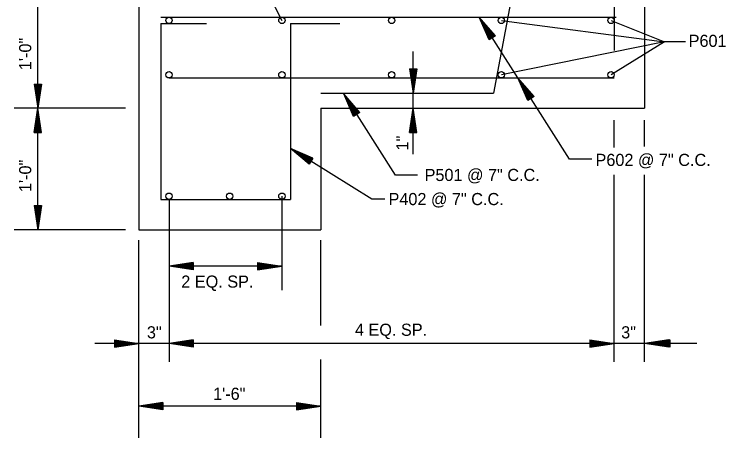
# Model space of a CAD drawing. Extents: x 714919 to 718439, y 1619644 to 1621844.
# Drawn here: x 717030 to 717616, y 1620465 to 1620814 of the extents above; entities that cross this region are included whole.
import ezdxf

# ---------------------------------------------------------------- set-up
doc = ezdxf.new("R2010")
doc.units = 0
doc.layers.add('R_Dimension', color=7, linetype='Continuous')
doc.layers.add('R_Draft', color=7, linetype='Continuous')

msp = doc.modelspace()

# ---------------------------------------------------------------- linework, layer by layer
at = {"layer": 'R_Dimension'}
for p, q in [((717426.61, 1620796.16), (717413.33, 1620811.42)), ((717421.55, 1620792.94), (717413.33, 1620811.42)), ((717426.19, 1620795.89), (717415.13, 1620808.6)), ((717421.97, 1620793.2), (717415.13, 1620808.6)), ((717422.4, 1620793.48), (717416.98, 1620805.7)), ((717425.76, 1620795.62), (717416.98, 1620805.7)), ((717425.34, 1620795.35), (717418.77, 1620802.89)), ((717422.82, 1620793.75), (717418.77, 1620802.89)), ((717423.25, 1620794.02), (717420.59, 1620800.03)), ((717424.9, 1620795.07), (717420.59, 1620800.03)), ((717426.61, 1620796.16), (717421.55, 1620792.94)), ((717423.68, 1620794.3), (717422.38, 1620797.21)), ((717424.48, 1620794.8), (717422.38, 1620797.21)), ((717355.85, 1620768.92), (717358.85, 1620748.92)), ((717355.85, 1620768.92), (717361.85, 1620768.92)), ((717356.35, 1620768.92), (717358.85, 1620752.26)), ((717356.86, 1620768.92), (717358.85, 1620755.7)), ((717357.36, 1620768.92), (717358.85, 1620759.03)), ((717357.88, 1620768.92), (717358.85, 1620762.42)), ((717358.38, 1620768.92), (717358.85, 1620765.76)), ((717361.85, 1620768.92), (717358.85, 1620748.92)), ((717359.83, 1620768.92), (717358.85, 1620762.42)), ((717360.84, 1620768.92), (717358.85, 1620755.7)), ((717361.35, 1620768.92), (717358.85, 1620752.26)), ((717360.34, 1620768.92), (717358.85, 1620759.03)), ((717359.32, 1620768.92), (717358.85, 1620765.76)), ((717458.46, 1620746.16), (717445.19, 1620761.42)), ((717453.4, 1620742.94), (717445.19, 1620761.42)), ((717458.04, 1620745.89), (717446.98, 1620758.6)), ((717453.82, 1620743.2), (717446.98, 1620758.6)), ((717046.74, 1620756.42), (717049.74, 1620736.42)), ((717046.74, 1620756.42), (717052.74, 1620756.42)), ((717047.24, 1620756.42), (717049.74, 1620739.76)), ((717047.75, 1620756.42), (717049.74, 1620743.2)), ((717048.25, 1620756.42), (717049.74, 1620746.53)), ((717048.77, 1620756.42), (717049.74, 1620749.92)), ((717049.27, 1620756.42), (717049.74, 1620753.26)), ((717052.74, 1620756.42), (717049.74, 1620736.42)), ((717050.72, 1620756.42), (717049.74, 1620749.92)), ((717051.73, 1620756.42), (717049.74, 1620743.2)), ((717052.24, 1620756.42), (717049.74, 1620739.76)), ((717051.23, 1620756.42), (717049.74, 1620746.53)), ((717050.21, 1620756.42), (717049.74, 1620753.26)), ((717454.25, 1620743.48), (717448.83, 1620755.7)), ((717457.61, 1620745.62), (717448.83, 1620755.7)), ((717457.19, 1620745.35), (717450.62, 1620752.89)), ((717454.67, 1620743.75), (717450.62, 1620752.89)), ((717314.94, 1620732.96), (717301.66, 1620748.22)), ((717309.88, 1620729.74), (717301.66, 1620748.22)), ((717455.1, 1620744.02), (717452.44, 1620750.03)), ((717456.75, 1620745.07), (717452.44, 1620750.03)), ((717458.46, 1620746.16), (717453.4, 1620742.94)), ((717455.54, 1620744.3), (717454.23, 1620747.21)), ((717456.33, 1620744.8), (717454.23, 1620747.21)), ((717314.52, 1620732.69), (717303.46, 1620745.4)), ((717310.3, 1620730.01), (717303.46, 1620745.4)), ((717310.73, 1620730.28), (717305.3, 1620742.5)), ((717314.09, 1620732.42), (717305.3, 1620742.5)), ((717046.74, 1620716.42), (717049.74, 1620736.42)), ((717052.74, 1620716.42), (717049.74, 1620736.42)), ((717313.66, 1620732.15), (717307.09, 1620739.69)), ((717311.15, 1620730.55), (717307.09, 1620739.69)), ((717311.58, 1620730.82), (717308.92, 1620736.83)), ((717313.23, 1620731.87), (717308.92, 1620736.83)), ((717355.85, 1620716.42), (717358.85, 1620736.42)), ((717361.85, 1620716.42), (717358.85, 1620736.42)), ((717047.24, 1620716.42), (717049.74, 1620733.08)), ((717047.75, 1620716.42), (717049.74, 1620729.64)), ((717052.24, 1620716.42), (717049.74, 1620733.08)), ((717051.73, 1620716.42), (717049.74, 1620729.64)), ((717314.94, 1620732.96), (717309.88, 1620729.74)), ((717312.01, 1620731.1), (717310.71, 1620734.01)), ((717312.8, 1620731.6), (717310.71, 1620734.01)), ((717356.35, 1620716.42), (717358.85, 1620733.08)), ((717356.86, 1620716.42), (717358.85, 1620729.64)), ((717361.35, 1620716.42), (717358.85, 1620733.08)), ((717360.84, 1620716.42), (717358.85, 1620729.64)), ((717048.25, 1620716.42), (717049.74, 1620726.31)), ((717048.77, 1620716.42), (717049.74, 1620722.92)), ((717051.23, 1620716.42), (717049.74, 1620726.31)), ((717050.72, 1620716.42), (717049.74, 1620722.92)), ((717357.36, 1620716.42), (717358.85, 1620726.31)), ((717357.88, 1620716.42), (717358.85, 1620722.92)), ((717360.34, 1620716.42), (717358.85, 1620726.31)), ((717359.83, 1620716.42), (717358.85, 1620722.92)), ((717049.27, 1620716.42), (717049.74, 1620719.58)), ((717050.21, 1620716.42), (717049.74, 1620719.58)), ((717358.38, 1620716.42), (717358.85, 1620719.58)), ((717359.32, 1620716.42), (717358.85, 1620719.58)), ((717046.74, 1620716.42), (717052.74, 1620716.42)), ((717355.85, 1620716.42), (717361.85, 1620716.42)), ((717276.36, 1620695.38), (717257.81, 1620703.43)), ((717273.18, 1620690.29), (717257.81, 1620703.43)), ((717276.09, 1620694.95), (717260.64, 1620701.66)), ((717273.44, 1620690.71), (717260.64, 1620701.66)), ((717273.71, 1620691.15), (717263.56, 1620699.84)), ((717275.82, 1620694.52), (717263.56, 1620699.84)), ((717275.56, 1620694.1), (717266.38, 1620698.07)), ((717273.98, 1620691.57), (717266.38, 1620698.07)), ((717274.25, 1620692), (717269.25, 1620696.28)), ((717275.28, 1620693.66), (717269.25, 1620696.28)), ((717274.52, 1620692.44), (717272.09, 1620694.51)), ((717275.02, 1620693.23), (717272.09, 1620694.51)), ((717276.36, 1620695.38), (717273.18, 1620690.29)), ((717046.74, 1620656.42), (717049.74, 1620636.42)), ((717046.74, 1620656.42), (717052.74, 1620656.42)), ((717047.24, 1620656.42), (717049.74, 1620639.76)), ((717047.75, 1620656.42), (717049.74, 1620643.2)), ((717048.25, 1620656.42), (717049.74, 1620646.53)), ((717048.77, 1620656.42), (717049.74, 1620649.92)), ((717049.27, 1620656.42), (717049.74, 1620653.26)), ((717052.74, 1620656.42), (717049.74, 1620636.42)), ((717050.72, 1620656.42), (717049.74, 1620649.92)), ((717051.73, 1620656.42), (717049.74, 1620643.2)), ((717052.24, 1620656.42), (717049.74, 1620639.76)), ((717051.23, 1620656.42), (717049.74, 1620646.53)), ((717050.21, 1620656.42), (717049.74, 1620653.26)), ((717177.81, 1620609.42), (717157.81, 1620606.42)), ((717177.81, 1620603.42), (717157.81, 1620606.42)), ((717177.81, 1620608.92), (717161.15, 1620606.42)), ((717177.81, 1620603.92), (717161.15, 1620606.42)), ((717177.81, 1620608.41), (717164.59, 1620606.42)), ((717177.81, 1620604.43), (717164.59, 1620606.42)), ((717177.81, 1620607.91), (717167.92, 1620606.42)), ((717177.81, 1620604.93), (717167.92, 1620606.42)), ((717177.81, 1620607.39), (717171.31, 1620606.42)), ((717177.81, 1620605.44), (717171.31, 1620606.42)), ((717177.81, 1620606.89), (717174.65, 1620606.42)), ((717177.81, 1620605.95), (717174.65, 1620606.42)), ((717177.81, 1620609.42), (717177.81, 1620603.42)), ((717230.78, 1620609.42), (717250.78, 1620606.42)), ((717230.78, 1620609.42), (717230.78, 1620603.42)), ((717230.78, 1620608.92), (717247.44, 1620606.42)), ((717230.78, 1620608.41), (717244, 1620606.42)), ((717230.78, 1620607.91), (717240.67, 1620606.42)), ((717230.78, 1620607.39), (717237.28, 1620606.42)), ((717230.78, 1620606.89), (717233.94, 1620606.42)), ((717230.78, 1620603.42), (717250.78, 1620606.42)), ((717230.78, 1620605.44), (717237.28, 1620606.42)), ((717230.78, 1620604.43), (717244, 1620606.42)), ((717230.78, 1620603.92), (717247.44, 1620606.42)), ((717230.78, 1620604.93), (717240.67, 1620606.42)), ((717230.78, 1620605.95), (717233.94, 1620606.42)), ((717112.81, 1620545.72), (717132.81, 1620542.72)), ((717112.81, 1620545.72), (717112.81, 1620539.72)), ((717112.81, 1620545.22), (717129.47, 1620542.72)), ((717112.81, 1620544.71), (717126.03, 1620542.72)), ((717112.81, 1620544.21), (717122.7, 1620542.72)), ((717112.81, 1620543.69), (717119.31, 1620542.72)), ((717112.81, 1620543.19), (717115.97, 1620542.72)), ((717112.81, 1620539.72), (717132.81, 1620542.72)), ((717112.81, 1620541.74), (717119.31, 1620542.72)), ((717112.81, 1620540.73), (717126.03, 1620542.72)), ((717112.81, 1620540.22), (717129.47, 1620542.72)), ((717112.81, 1620541.23), (717122.7, 1620542.72)), ((717112.81, 1620542.25), (717115.97, 1620542.72)), ((717177.81, 1620545.72), (717157.81, 1620542.72)), ((717177.81, 1620539.72), (717157.81, 1620542.72)), ((717177.81, 1620545.22), (717161.15, 1620542.72)), ((717177.81, 1620540.22), (717161.15, 1620542.72)), ((717177.81, 1620544.71), (717164.59, 1620542.72)), ((717177.81, 1620540.73), (717164.59, 1620542.72)), ((717177.81, 1620544.21), (717167.92, 1620542.72)), ((717177.81, 1620541.23), (717167.92, 1620542.72)), ((717177.81, 1620543.69), (717171.31, 1620542.72)), ((717177.81, 1620541.74), (717171.31, 1620542.72)), ((717177.81, 1620543.19), (717174.65, 1620542.72)), ((717177.81, 1620542.25), (717174.65, 1620542.72)), ((717177.81, 1620545.72), (717177.81, 1620539.72)), ((717504.48, 1620545.72), (717524.48, 1620542.72)), ((717504.48, 1620545.72), (717504.48, 1620539.72)), ((717504.48, 1620545.22), (717521.14, 1620542.72)), ((717504.48, 1620544.71), (717517.7, 1620542.72)), ((717504.48, 1620544.21), (717514.37, 1620542.72)), ((717504.48, 1620543.69), (717510.98, 1620542.72)), ((717504.48, 1620543.19), (717507.64, 1620542.72)), ((717504.48, 1620539.72), (717524.48, 1620542.72)), ((717504.48, 1620541.74), (717510.98, 1620542.72)), ((717504.48, 1620540.73), (717517.7, 1620542.72)), ((717504.48, 1620540.22), (717521.14, 1620542.72)), ((717504.48, 1620541.23), (717514.37, 1620542.72)), ((717504.48, 1620542.25), (717507.64, 1620542.72)), ((717569.48, 1620545.72), (717549.48, 1620542.72)), ((717569.48, 1620539.72), (717549.48, 1620542.72)), ((717570.23, 1620545.72), (717550.23, 1620542.72)), ((717570.23, 1620539.72), (717550.23, 1620542.72)), ((717569.48, 1620545.22), (717552.82, 1620542.72)), ((717569.48, 1620540.22), (717552.82, 1620542.72)), ((717570.23, 1620545.22), (717553.57, 1620542.72)), ((717570.23, 1620540.22), (717553.57, 1620542.72)), ((717569.48, 1620544.71), (717556.26, 1620542.72)), ((717569.48, 1620540.73), (717556.26, 1620542.72)), ((717570.23, 1620544.71), (717557.01, 1620542.72)), ((717570.23, 1620540.73), (717557.01, 1620542.72)), ((717569.48, 1620544.21), (717559.59, 1620542.72)), ((717569.48, 1620541.23), (717559.59, 1620542.72)), ((717570.23, 1620544.21), (717560.34, 1620542.72)), ((717570.23, 1620541.23), (717560.34, 1620542.72)), ((717569.48, 1620543.69), (717562.98, 1620542.72)), ((717569.48, 1620541.74), (717562.98, 1620542.72)), ((717570.23, 1620543.69), (717563.73, 1620542.72)), ((717570.23, 1620541.74), (717563.73, 1620542.72)), ((717569.48, 1620543.19), (717566.32, 1620542.72)), ((717569.48, 1620542.25), (717566.32, 1620542.72)), ((717570.23, 1620543.19), (717567.07, 1620542.72)), ((717570.23, 1620542.25), (717567.07, 1620542.72)), ((717569.48, 1620545.72), (717569.48, 1620539.72)), ((717570.23, 1620545.72), (717570.23, 1620539.72)), ((717152.81, 1620494.09), (717132.81, 1620491.09)), ((717152.81, 1620494.09), (717152.81, 1620488.09)), ((717262.81, 1620494.09), (717282.81, 1620491.09)), ((717262.81, 1620494.09), (717262.81, 1620488.09)), ((717152.81, 1620488.09), (717132.81, 1620491.09)), ((717152.81, 1620493.59), (717136.15, 1620491.09)), ((717152.81, 1620488.59), (717136.15, 1620491.09)), ((717152.81, 1620493.08), (717139.59, 1620491.09)), ((717152.81, 1620489.1), (717139.59, 1620491.09)), ((717152.81, 1620492.58), (717142.92, 1620491.09)), ((717152.81, 1620489.6), (717142.92, 1620491.09)), ((717152.81, 1620492.06), (717146.31, 1620491.09)), ((717152.81, 1620490.11), (717146.31, 1620491.09)), ((717152.81, 1620491.56), (717149.65, 1620491.09)), ((717152.81, 1620490.62), (717149.65, 1620491.09)), ((717262.81, 1620493.59), (717279.47, 1620491.09)), ((717262.81, 1620493.08), (717276.03, 1620491.09)), ((717262.81, 1620492.58), (717272.7, 1620491.09)), ((717262.81, 1620492.06), (717269.31, 1620491.09)), ((717262.81, 1620491.56), (717265.97, 1620491.09)), ((717262.81, 1620488.09), (717282.81, 1620491.09)), ((717262.81, 1620490.11), (717269.31, 1620491.09)), ((717262.81, 1620489.1), (717276.03, 1620491.09)), ((717262.81, 1620488.59), (717279.47, 1620491.09)), ((717262.81, 1620489.6), (717272.7, 1620491.09)), ((717262.81, 1620490.62), (717265.97, 1620491.09))]:
    msp.add_line(p, q, dxfattribs=at)
at = {"layer": 'R_Draft'}
for p, q in [((717549.48, 1621186.42), (717549.48, 1620736.42)), ((717466.66, 1620968.01), (717424.92, 1620748.92)), ((717524.48, 1620962.55), (717524.48, 1620783.94)), ((717049.74, 1620736.42), (717049.74, 1620836.42)), ((717132.81, 1620836.42), (717132.81, 1620636.42)), ((717151.17, 1620811.42), (717525.96, 1620811.42)), ((717445.19, 1620761.42), (717413.33, 1620811.42)), ((717151.17, 1620806.21), (717151.17, 1620661.42)), ((717151.17, 1620806.21), (717188.57, 1620806.21)), ((717257.81, 1620806.21), (717257.81, 1620661.42)), ((717257.81, 1620806.21), (717298.47, 1620806.21)), ((717583.21, 1620791.3), (717565.95, 1620791.3)), ((717358.85, 1620698.68), (717358.85, 1620783.24)), ((717157.81, 1620761.42), (717524.48, 1620761.42)), ((717487.77, 1620694.56), (717445.19, 1620761.42)), ((717282.81, 1620748.92), (717424.92, 1620748.92)), ((717344.25, 1620681.36), (717301.66, 1620748.22)), ((717122.02, 1620736.42), (717030.32, 1620736.42)), ((717049.74, 1620636.42), (717049.74, 1620736.42)), ((717282.81, 1620736.42), (717549.48, 1620736.42)), ((717282.81, 1620736.42), (717282.81, 1620636.42)), ((717524.48, 1620704.26), (717524.48, 1620726.75)), ((717549.48, 1620705.07), (717549.48, 1620726.75)), ((717506.09, 1620694.56), (717487.77, 1620694.56)), ((717362.57, 1620681.36), (717344.25, 1620681.36)), ((717524.48, 1620527.65), (717524.48, 1620681.71)), ((717549.48, 1620527.65), (717549.48, 1620681.71)), ((717250.78, 1620664.02), (717250.78, 1620586.68)), ((717151.17, 1620661.42), (717257.81, 1620661.42)), ((717157.81, 1620661.42), (717157.81, 1620527.65)), ((717122.02, 1620636.42), (717030.32, 1620636.42)), ((717132.81, 1620636.42), (717282.81, 1620636.42)), ((717132.81, 1620465.01), (717132.81, 1620627.81)), ((717282.81, 1620557.49), (717282.81, 1620627.81)), ((717250.78, 1620606.42), (717157.81, 1620606.42)), ((717157.81, 1620542.72), (717096.81, 1620542.72)), ((717282.81, 1620542.72), (717157.81, 1620542.72)), ((717524.48, 1620542.72), (717282.81, 1620542.72)), ((717592.42, 1620542.72), (717524.48, 1620542.72)), ((717282.81, 1620465.01), (717282.81, 1620529.47)), ((717282.81, 1620491.09), (717132.81, 1620491.09))]:
    msp.add_line(p, q, dxfattribs=at)
for points in [[(717217.03, 1620874.91), (717250.78, 1620808.81)], [(717431.51, 1620808.81), (717565.95, 1620791.3), (717431.51, 1620764.02)], [(717521.87, 1620808.81), (717565.95, 1620791.3), (717521.87, 1620764.02)], [(717335.48, 1620661.51), (717324.91, 1620661.51), (717257.81, 1620703.43)]]:
    msp.add_lwpolyline(points, dxfattribs=at)
for centre in [(717157.81, 1620808.81), (717250.78, 1620808.81), (717341.14, 1620808.81), (717431.51, 1620808.81), (717521.87, 1620808.81), (717157.81, 1620764.02), (717250.78, 1620764.02), (717341.14, 1620764.02), (717431.51, 1620764.02), (717521.87, 1620764.02), (717157.81, 1620664.02), (717207.81, 1620664.02), (717250.78, 1620664.02)]:
    msp.add_circle(centre, 2.6, dxfattribs=at)

# ---------------------------------------------------------------- texts
for s, p in [('1\'-0"', (717044.36, 1620767.88)), ('1"', (717354.97, 1620701.66)), ('1\'-0"', (717044.36, 1620667.42))]:
    msp.add_text(s, height=10, rotation=90, dxfattribs=at).set_placement(p)
for s, p in [('P601', (717585.77, 1620787.03)), ('P602 @ 7" C.C.', (717509.06, 1620688.92)), ('P501 @ 7" C.C.', (717368.3, 1620676.53)), ('P402 @ 7" C.C.', (717338.59, 1620656.66)), ('2 EQ. SP.', (717167.91, 1620588.67)), ('4 EQ. SP.', (717310.93, 1620549.01)), ('3"', (717139.58, 1620546.88)), ('3"', (717530.19, 1620546.88)), ('1\'-6"', (717194.12, 1620496.25))]:
    msp.add_text(s, height=10, dxfattribs=at).set_placement(p)

doc.saveas('drawing.dxf')
